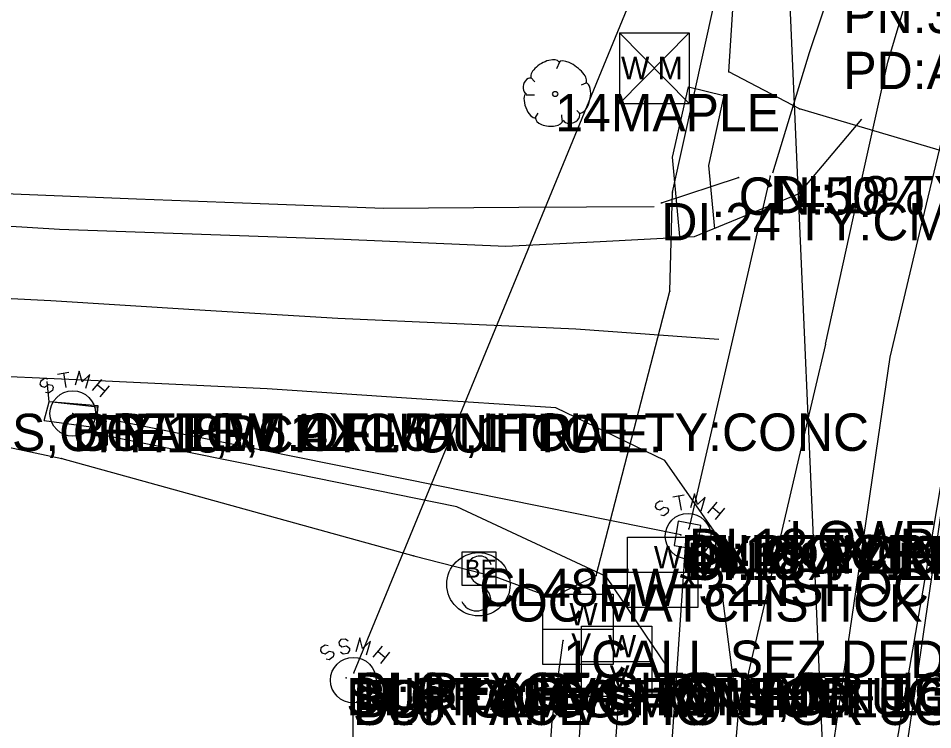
# Model space of a CAD drawing. Extents: x 997398 to 1003416, y 334596 to 337085.
# Drawn here: x 999151.8 to 999274.2, y 335545.4 to 335640.6 of the extents above; entities that cross this region are included whole.
import ezdxf

# ---------------------------------------------------------------- set-up
doc = ezdxf.new("R2010")
doc.units = 0
for name, color, linetype in [('Default', 7, 'Continuous'), ('S_DITCHLINE', 7, 'Continuous'), ('S_DRG_PT_SYM', 7, 'Continuous'), ('S_EDGE_CONCRETE', 7, 'Continuous'), ('S_EDGE_PAVEMENT', 7, 'Continuous'), ('S_ELECTRIC_UTILITIES', 7, 'Continuous'), ('S_ELECTRIC_UTILITIES_ANNOT', 7, 'Continuous'), ('S_FIBER_OPTIC_CABLE', 7, 'Continuous'), ('S_GAS_UTILITIES', 7, 'Continuous'), ('S_GAS_UTILITIES_ANNOT', 7, 'Continuous'), ('S_GRD_PT_SYM', 7, 'Continuous'), ('S_MANHOLE_ANNOT', 7, 'Continuous'), ('S_MISC_TOPO_POINT', 7, 'Continuous'), ('S_PAVEMENT_CROWN', 7, 'Continuous'), ('S_PRIMARY_CTL_ANNOT', 7, 'Continuous'), ('S_SANITARY_SEWER', 7, 'Continuous'), ('S_SANITARY_SEWER_ANNOT', 7, 'Continuous'), ('S_SHOULDER', 7, 'Continuous'), ('S_SIDE_DRAIN', 7, 'Continuous'), ('S_SIDE_DRAIN_ANNOT', 7, 'Continuous'), ('S_SIDEWALK', 7, 'Continuous'), ('S_SIGN', 7, 'Continuous'), ('S_SIGN_ANNOT', 7, 'Continuous'), ('S_STORM_SEWER', 7, 'Continuous'), ('S_STORM_SEWER_ANNOT', 7, 'Continuous'), ('S_TREE', 7, 'Continuous'), ('S_TREE_ANNOT', 7, 'Continuous'), ('S_UTILITY_POLE_ANNOT', 7, 'Continuous'), ('S_UTL_PT_SYM', 7, 'Continuous'), ('S_WATER_UTILITIES', 7, 'Continuous')]:
    doc.layers.add(name, color=color, linetype=linetype)

msp = doc.modelspace()

# ---------------------------------------------------------------- linework, layer by layer
at = {"layer": 'Default'}
msp.add_line((999272.07, 335256.17), (999254.77, 335651.12), dxfattribs=at)
at = {"layer": 'S_DITCHLINE'}
for points in [[(999287.81, 335737.53), (999281.43, 335714.1), (999277.48, 335699.31), (999273.53, 335684.53), (999269.56, 335672.01), (999265.58, 335659.49), (999257.69, 335636), (999252.77, 335619.88)], [(999236.93, 335615.36), (999218.82, 335615.26), (999200.71, 335615.16), (999184.18, 335615.77), (999167.64, 335616.38), (999153.3, 335616.96), (999138.96, 335617.54), (999118.05, 335618.98), (999097.13, 335620.43)]]:
    msp.add_lwpolyline(points, dxfattribs=at)
at = {"layer": 'S_DRG_PT_SYM'}
for points in [[(999248.25, 335619.3), (999248.25, 335619.35), (999248.25, 335619.3), (999248.2, 335619.3), (999248.25, 335619.3), (999248.25, 335619.25), (999248.25, 335619.3), (999248.3, 335619.3)], [(999252.48, 335619.48), (999252.48, 335619.53), (999252.48, 335619.48), (999252.43, 335619.48), (999252.48, 335619.48), (999252.48, 335619.43), (999252.48, 335619.48), (999252.53, 335619.48)], [(999237.91, 335615.88), (999237.91, 335615.93), (999237.91, 335615.88), (999237.86, 335615.88), (999237.91, 335615.88), (999237.91, 335615.83), (999237.91, 335615.88), (999237.96, 335615.88)], [(999241.18, 335570.41), (999241.18, 335570.46), (999241.18, 335570.41), (999241.13, 335570.41), (999241.18, 335570.41), (999241.18, 335570.36), (999241.18, 335570.41), (999241.23, 335570.41)]]:
    msp.add_lwpolyline(points, dxfattribs=at)
at = {"layer": 'S_EDGE_CONCRETE'}
for points in [[(999155.26, 335586.75), (999155.93, 335589.24)], [(999155.26, 335586.75), (999162.22, 335585.84), (999162.48, 335588.73)], [(999162.48, 335588.73), (999155.93, 335589.24)], [(999240.17, 335573.28), (999239.64, 335570.01), (999242.69, 335569.51), (999243.18, 335572.72)], [(999243.18, 335572.72), (999240.17, 335573.28)]]:
    msp.add_lwpolyline(points, dxfattribs=at)
at = {"layer": 'S_EDGE_PAVEMENT'}
for points in [[(999259.87, 335596.96), (999264.04, 335615.85), (999268.21, 335634.73), (999272.57, 335649.27), (999276.93, 335663.8), (999281.3, 335678.34), (999285.66, 335692.87), (999290.47, 335705.41), (999295.28, 335717.95), (999300.08, 335730.5), (999304.89, 335743.04), (999311.07, 335757.48), (999317.24, 335771.92), (999323.96, 335787.59), (999330.67, 335803.27), (999334.33, 335812.1)], [(999077.15, 335619.41), (999094.78, 335617.29), (999112.4, 335615.17), (999134.86, 335613.78), (999157.33, 335612.39), (999176.33, 335611.71), (999195.33, 335611.02), (999217.09, 335610.08), (999229.71, 335610.74), (999242.32, 335611.39), (999256.34, 335617.13), (999264.73, 335627.09)], [(999242.46, 335474.78), (999243.48, 335492.06), (999244.65, 335505.83), (999245.83, 335519.59), (999247.01, 335533.36), (999248.18, 335547.12), (999246.58, 335559.54), (999244.98, 335571.95), (999238.35, 335581.43), (999223.76, 335588.45), (999204.45, 335589.72), (999185.14, 335591), (999163.46, 335592.01), (999141.78, 335593.03), (999120.82, 335594.21), (999099.85, 335595.38), (999086.61, 335596.71), (999073.36, 335598.03)], [(999259.87, 335596.96), (999256.94, 335584.5), (999254.02, 335572.04), (999251.1, 335559.58), (999248.18, 335547.12)], [(999250.53, 335290.61), (999251.9, 335310.31), (999253.28, 335330), (999254.66, 335349.69), (999256.03, 335369.39), (999256.96, 335383.69), (999257.89, 335397.99), (999259.31, 335422.72), (999260.17, 335436.32), (999261.04, 335449.92), (999261.9, 335463.52), (999262.77, 335477.12), (999265.06, 335501.55), (999266.67, 335519.12), (999268.27, 335536.68), (999270.61, 335550.38), (999272.95, 335564.07), (999275.29, 335577.76), (999277.63, 335591.45)], [(999268.87, 335320.6), (999263.53, 335329.26), (999260.4, 335340), (999260.03, 335350.15), (999261.25, 335369.32), (999262.19, 335383.58), (999263.12, 335397.84), (999266.91, 335402.13), (999261.38, 335422.51), (999262.14, 335435.92), (999262.89, 335449.33), (999263.64, 335462.75), (999264.4, 335476.16), (999272.66, 335481.44), (999281.46, 335481.65), (999283.33, 335495.44), (999285.2, 335509.23), (999269.56, 335528.03), (999269.81, 335536.47), (999271.83, 335550.21), (999273.84, 335563.95), (999275.86, 335577.69), (999277.88, 335591.43)]]:
    msp.add_lwpolyline(points, dxfattribs=at)
at = {"layer": 'S_ELECTRIC_UTILITIES'}
msp.add_lwpolyline([(999211.25, 335564.67), (999211.25, 335569.17), (999215.75, 335569.17), (999215.75, 335564.67)], close=True, dxfattribs=at)
at = {"layer": 'S_FIBER_OPTIC_CABLE'}
for p, q in [((999239.4, 335617.34), (999245.02, 335642.72)), ((999246.94, 335633.43), (999247.58, 335643.26)), ((999256.41, 335628.49), (999246.94, 335633.43)), ((999286.13, 335619.67), (999256.41, 335628.49)), ((999239.02, 335604.06), (999239.4, 335617.34)), ((999229.16, 335566.02), (999239.02, 335604.06)), ((999113.2, 335591.12), (999157.62, 335581.67)), ((999157.62, 335581.67), (999204.77, 335568.66)), ((999204.77, 335568.66), (999215.76, 335565.85)), ((999215.76, 335565.85), (999223.21, 335563.09)), ((999223.21, 335563.09), (999229.16, 335566.02))]:
    msp.add_line(p, q, dxfattribs=at)
at = {"layer": 'S_GAS_UTILITIES'}
for p, q in [((999223.28, 335546.56), (999224.76, 335557.3)), ((999220.7, 335507.17), (999223.28, 335546.56))]:
    msp.add_line(p, q, dxfattribs=at)
at = {"layer": 'S_GRD_PT_SYM'}
for points in [[(999161.18, 335587.48), (999161.18, 335587.53), (999161.18, 335587.48), (999161.13, 335587.48), (999161.18, 335587.48), (999161.18, 335587.43), (999161.18, 335587.48), (999161.23, 335587.48)], [(999255.04, 335573.32), (999255.04, 335573.37), (999255.04, 335573.32), (999254.99, 335573.32), (999255.04, 335573.32), (999255.04, 335573.27), (999255.04, 335573.32), (999255.09, 335573.32)], [(999240.51, 335571.44), (999240.51, 335571.49), (999240.51, 335571.44), (999240.46, 335571.44), (999240.51, 335571.44), (999240.51, 335571.39), (999240.51, 335571.44), (999240.56, 335571.44)], [(999241.58, 335572.28), (999241.58, 335572.33), (999241.58, 335572.28), (999241.53, 335572.28), (999241.58, 335572.28), (999241.58, 335572.23), (999241.58, 335572.28), (999241.63, 335572.28)], [(999241.29, 335570.42), (999241.29, 335570.47), (999241.29, 335570.42), (999241.24, 335570.42), (999241.29, 335570.42), (999241.29, 335570.37), (999241.29, 335570.42), (999241.34, 335570.42)], [(999196.73, 335553), (999196.73, 335553.05), (999196.73, 335553), (999196.68, 335553), (999196.73, 335553), (999196.73, 335552.95), (999196.73, 335553), (999196.78, 335553)], [(999195.72, 335552.31), (999195.72, 335552.36), (999195.72, 335552.31), (999195.67, 335552.31), (999195.72, 335552.31), (999195.72, 335552.26), (999195.72, 335552.31), (999195.77, 335552.31)], [(999196.62, 335551), (999196.62, 335551.05), (999196.62, 335551), (999196.57, 335551), (999196.62, 335551), (999196.62, 335550.95), (999196.62, 335551), (999196.67, 335551)]]:
    msp.add_lwpolyline(points, dxfattribs=at)
at = {"layer": 'S_PAVEMENT_CROWN'}
for points in [[(999240.93, 335269.15), (999242.42, 335292.45), (999243.36, 335312.31), (999244.3, 335332.17), (999245.73, 335356.52), (999247.17, 335380.88), (999248.33, 335401.35), (999249.49, 335421.83), (999250.52, 335439.55), (999251.54, 335457.27), (999252.57, 335474.99), (999253.6, 335492.71), (999255.46, 335505.53), (999257.33, 335518.35), (999259.19, 335531.16), (999261.06, 335543.98), (999262.92, 335556.8), (999264.79, 335569.61), (999266.65, 335582.43), (999268.52, 335595.25), (999272.87, 335613.5), (999277.22, 335631.74), (999281.77, 335646.2)], [(999074.89, 335609.01), (999093.33, 335607.02), (999111.77, 335605.03), (999133.96, 335603.93), (999156.15, 335602.83), (999175.37, 335601.64), (999194.6, 335600.46), (999210.53, 335599.74), (999226.46, 335599.02), (999245.58, 335597.67)]]:
    msp.add_lwpolyline(points, dxfattribs=at)
at = {"layer": 'S_SANITARY_SEWER'}
for p, q in [((999196.73, 335553), (999235.68, 335647.6)), ((999192.88, 335556.7), (999192.33, 335556.31)), ((999193.3, 335556.62), (999192.88, 335556.7)), ((999192.33, 335556.31), (999192.26, 335555.92)), ((999192.26, 335555.92), (999192.45, 335555.65)), ((999192.45, 335555.65), (999192.88, 335555.53)), ((999192.88, 335555.53), (999193.42, 335555.88)), ((999193.42, 335555.88), (999193.88, 335555.8)), ((999193.88, 335555.8), (999194.04, 335555.53)), ((999194.04, 335555.53), (999193.96, 335555.11)), ((999199.31, 335555.07), (999200.55, 335556.54)), ((999199.97, 335555.84), (999200.94, 335555.03)), ((999201.52, 335555.73), (999200.28, 335554.25)), ((999193.42, 335554.72), (999193.03, 335554.8)), ((999193.96, 335555.11), (999193.42, 335554.72)), ((999197.31, 335352.9), (999196.62, 335551))]:
    msp.add_line(p, q, dxfattribs=at)
for points in [[(999195.98, 335557.24), (999195.63, 335557.51), (999194.97, 335557.43), (999194.74, 335557.08), (999194.77, 335556.77), (999195.12, 335556.46), (999195.74, 335556.58), (999196.13, 335556.27), (999196.17, 335555.96), (999195.9, 335555.57), (999195.28, 335555.49), (999194.93, 335555.77)], [(999198.42, 335555.38), (999198.96, 335557.24), (999197.91, 335556.23), (999197.53, 335557.66), (999196.98, 335555.8)]]:
    msp.add_lwpolyline(points, dxfattribs=at)
msp.add_circle((999196.66, 335552), 3.05, dxfattribs=at)
at = {"layer": 'S_SHOULDER'}
msp.add_lwpolyline([(999238.81, 335553.62), (999230.53, 335565.88), (999210.52, 335575.21), (999186.37, 335580.1), (999162.21, 335584.98), (999162.42, 335588.53), (999155.93, 335589.24), (999155.69, 335591.99)], dxfattribs=at)
at = {"layer": 'S_SIDE_DRAIN'}
for p, q in [((999237.91, 335615.88), (999248.25, 335619.3)), ((999252.48, 335619.48), (999241.58, 335572.28)), ((999233.26, 335456.06), (999241.18, 335570.41))]:
    msp.add_line(p, q, dxfattribs=at)
at = {"layer": 'S_SIDEWALK'}
for points in [[(999240.36, 335611.38), (999239.4, 335622.03), (999241.55, 335631.45), (999246.25, 335630.25), (999244.2, 335620.92), (999245.02, 335612.43)], [(999214.01, 335280.58), (999214.8, 335292.62), (999216.16, 335313.46), (999217.52, 335334.3), (999218.07, 335347.06), (999218.63, 335359.82), (999222.21, 335371.88), (999225.78, 335383.94), (999224.2, 335403.9), (999222.62, 335423.86), (999222.83, 335441.35), (999223.04, 335458.84), (999223.26, 335476.33), (999223.47, 335493.82), (999224.42, 335507.61), (999225.37, 335521.4), (999226.32, 335535.18), (999227.27, 335548.97)], [(999225.73, 335271.38), (999218.89, 335281.67), (999219.66, 335292.48), (999220.98, 335313.22), (999222.31, 335333.97), (999223.3, 335346.79), (999224.29, 335359.6), (999230.64, 335383.76), (999229.05, 335404.13), (999227.47, 335424.5), (999227.67, 335441.74), (999227.86, 335458.99), (999228.06, 335476.23), (999228.26, 335493.48), (999229.22, 335507.16), (999230.18, 335520.85), (999231.14, 335534.54), (999232.1, 335548.22)]]:
    msp.add_lwpolyline(points, dxfattribs=at)
at = {"layer": 'S_SIGN'}
msp.add_circle((999213.42, 335564.84), 4.24, dxfattribs=at)
for centre, radius, start, end in [((999213.55, 335567), 1.62, 16.5258, 156.8957), ((999214.58, 335567.1), 2.55, 167.1196, 241.9813), ((999212.72, 335562.56), 2.38, 358.6529, 73.7063), ((999213.16, 335563.44), 2.17, 204.641, 335.359)]:
    msp.add_arc(centre, radius, start, end, dxfattribs=at)
at = {"layer": 'S_STORM_SEWER'}
for p, q in [((999155.32, 335592.39), (999154.78, 335592)), ((999155.74, 335592.31), (999155.32, 335592.39)), ((999157.06, 335592.97), (999158.57, 335593.24)), ((999157.84, 335593.13), (999158.19, 335591.19)), ((999161.75, 335590.76), (999162.99, 335592.24)), ((999154.78, 335592), (999154.7, 335591.62)), ((999154.7, 335591.62), (999154.89, 335591.35)), ((999154.89, 335591.35), (999155.32, 335591.23)), ((999155.32, 335591.23), (999155.86, 335591.58)), ((999155.86, 335591.58), (999156.33, 335591.5)), ((999156.33, 335591.5), (999156.48, 335591.23)), ((999156.48, 335591.23), (999156.4, 335590.8)), ((999162.41, 335591.54), (999163.38, 335590.73)), ((999163.96, 335591.42), (999162.72, 335589.95)), ((999155.86, 335590.42), (999155.47, 335590.49)), ((999156.4, 335590.8), (999155.86, 335590.42)), ((999240.51, 335571.44), (999161.18, 335587.48)), ((999239.44, 335576.56), (999240.95, 335576.83)), ((999240.21, 335576.71), (999240.56, 335574.77)), ((999237.15, 335575.59), (999237.07, 335575.2)), ((999237.07, 335575.2), (999237.27, 335574.93)), ((999237.69, 335575.97), (999237.15, 335575.59)), ((999238.12, 335575.9), (999237.69, 335575.97)), ((999237.69, 335574.81), (999238.24, 335575.16)), ((999238.24, 335575.16), (999238.7, 335575.08)), ((999238.7, 335575.08), (999238.86, 335574.81)), ((999244.13, 335574.35), (999245.37, 335575.82)), ((999244.79, 335575.12), (999245.75, 335574.31)), ((999237.27, 335574.93), (999237.69, 335574.81)), ((999238.24, 335574), (999237.85, 335574.08)), ((999238.78, 335574.39), (999238.24, 335574)), ((999238.86, 335574.81), (999238.78, 335574.39)), ((999246.34, 335575.01), (999245.1, 335573.53))]:
    msp.add_line(p, q, dxfattribs=at)
for points in [[(999160.86, 335591.07), (999161.4, 335592.93), (999160.36, 335591.93), (999159.97, 335593.36), (999159.43, 335591.5)], [(999243.24, 335574.66), (999243.78, 335576.52), (999242.73, 335575.51), (999242.34, 335576.94), (999241.8, 335575.08)]]:
    msp.add_lwpolyline(points, dxfattribs=at)
for centre in [(999159.1, 335587.7), (999241.48, 335571.28)]:
    msp.add_circle(centre, 3.05, dxfattribs=at)
at = {"layer": 'S_TREE'}
for p, q in [((999224.25, 335634.72), (999223.86, 335633.86)), ((999220.45, 335632.7), (999220.95, 335632.12)), ((999227.81, 335631.93), (999227.15, 335631.66)), ((999219.79, 335630.38), (999220.91, 335630.38)), ((999220.95, 335627.2), (999221.42, 335627.9)), ((999224.63, 335626.93), (999224.56, 335627.7)), ((999227.04, 335627.82), (999226.57, 335628.25))]:
    msp.add_line(p, q, dxfattribs=at)
msp.add_circle((999223.69, 335630.47), 0.341, dxfattribs=at)
for centre, major_axis, ratio, start_param, end_param in [((999222.35, 335633.67), (1.86, 1.08), 0.471018, 0, 3.141593), ((999226.01, 335633.35), (-1.81, 1.36), 0.405113, 3.141593, 6.283186), ((999220.12, 335631.56), (0.31, 1.03), 0.646762, 0, 3.141593), ((999227.36, 335629.94), (0.46, 2.04), 0.482994, 3.141593, 6.283185), ((999220.42, 335628.91), (-0.61, 1.6), 0.420543, 6.283185, 9.424777), ((999225.84, 335627.42), (1.09, 0.46), 0.711534, 3.141592, 6.283185), ((999222.88, 335627.13), (-1.83, 0.19), 0.529943, 0, 3.141593)]:
    msp.add_ellipse(centre, major_axis=major_axis, ratio=ratio, start_param=start_param, end_param=end_param, dxfattribs=at)
at = {"layer": 'S_UTL_PT_SYM'}
for points in [[(999246.94, 335633.43), (999246.94, 335633.48), (999246.94, 335633.43), (999246.89, 335633.43), (999246.94, 335633.43), (999246.94, 335633.38), (999246.94, 335633.43), (999246.99, 335633.43)], [(999256.41, 335628.49), (999256.41, 335628.54), (999256.41, 335628.49), (999256.36, 335628.49), (999256.41, 335628.49), (999256.41, 335628.44), (999256.41, 335628.49), (999256.46, 335628.49)], [(999239.4, 335617.34), (999239.4, 335617.39), (999239.4, 335617.34), (999239.35, 335617.34), (999239.4, 335617.34), (999239.4, 335617.29), (999239.4, 335617.34), (999239.45, 335617.34)], [(999239.02, 335604.06), (999239.02, 335604.11), (999239.02, 335604.06), (999238.97, 335604.06), (999239.02, 335604.06), (999239.02, 335604.01), (999239.02, 335604.06), (999239.07, 335604.06)], [(999159.1, 335587.7), (999159.1, 335587.75), (999159.1, 335587.7), (999159.05, 335587.7), (999159.1, 335587.7), (999159.1, 335587.65), (999159.1, 335587.7), (999159.15, 335587.7)], [(999161.18, 335587.48), (999161.18, 335587.53), (999161.18, 335587.48), (999161.13, 335587.48), (999161.18, 335587.48), (999161.18, 335587.43), (999161.18, 335587.48), (999161.23, 335587.48)], [(999157.62, 335581.67), (999157.62, 335581.72), (999157.62, 335581.67), (999157.57, 335581.67), (999157.62, 335581.67), (999157.62, 335581.62), (999157.62, 335581.67), (999157.67, 335581.67)], [(999255.04, 335573.32), (999255.04, 335573.37), (999255.04, 335573.32), (999254.99, 335573.32), (999255.04, 335573.32), (999255.04, 335573.27), (999255.04, 335573.32), (999255.09, 335573.32)], [(999240.51, 335571.44), (999240.51, 335571.49), (999240.51, 335571.44), (999240.46, 335571.44), (999240.51, 335571.44), (999240.51, 335571.39), (999240.51, 335571.44), (999240.56, 335571.44)], [(999241.58, 335572.28), (999241.58, 335572.33), (999241.58, 335572.28), (999241.53, 335572.28), (999241.58, 335572.28), (999241.58, 335572.23), (999241.58, 335572.28), (999241.63, 335572.28)], [(999241.29, 335570.42), (999241.29, 335570.47), (999241.29, 335570.42), (999241.24, 335570.42), (999241.29, 335570.42), (999241.29, 335570.37), (999241.29, 335570.42), (999241.34, 335570.42)], [(999241.48, 335571.28), (999241.48, 335571.33), (999241.48, 335571.28), (999241.43, 335571.28), (999241.48, 335571.28), (999241.48, 335571.23), (999241.48, 335571.28), (999241.53, 335571.28)], [(999204.77, 335568.66), (999204.77, 335568.71), (999204.77, 335568.66), (999204.72, 335568.66), (999204.77, 335568.66), (999204.77, 335568.61), (999204.77, 335568.66), (999204.82, 335568.66)], [(999215.76, 335565.85), (999215.76, 335565.9), (999215.76, 335565.85), (999215.71, 335565.85), (999215.76, 335565.85), (999215.76, 335565.8), (999215.76, 335565.85), (999215.81, 335565.85)], [(999229.16, 335566.02), (999229.16, 335566.07), (999229.16, 335566.02), (999229.11, 335566.02), (999229.16, 335566.02), (999229.16, 335565.97), (999229.16, 335566.02), (999229.21, 335566.02)], [(999223.21, 335563.09), (999223.21, 335563.14), (999223.21, 335563.09), (999223.16, 335563.09), (999223.21, 335563.09), (999223.21, 335563.04), (999223.21, 335563.09), (999223.26, 335563.09)], [(999224.76, 335557.3), (999224.76, 335557.35), (999224.76, 335557.3), (999224.71, 335557.3), (999224.76, 335557.3), (999224.76, 335557.25), (999224.76, 335557.3), (999224.81, 335557.3)], [(999196.73, 335553), (999196.73, 335553.05), (999196.73, 335553), (999196.68, 335553), (999196.73, 335553), (999196.73, 335552.95), (999196.73, 335553), (999196.78, 335553)], [(999195.72, 335552.31), (999195.72, 335552.36), (999195.72, 335552.31), (999195.67, 335552.31), (999195.72, 335552.31), (999195.72, 335552.26), (999195.72, 335552.31), (999195.77, 335552.31)], [(999196.66, 335552), (999196.66, 335552.05), (999196.66, 335552), (999196.61, 335552), (999196.66, 335552), (999196.66, 335551.96), (999196.66, 335552), (999196.71, 335552)], [(999196.62, 335551), (999196.62, 335551.05), (999196.62, 335551), (999196.57, 335551), (999196.62, 335551), (999196.62, 335550.95), (999196.62, 335551), (999196.67, 335551)], [(999223.28, 335546.56), (999223.28, 335546.61), (999223.28, 335546.56), (999223.23, 335546.56), (999223.28, 335546.56), (999223.28, 335546.51), (999223.28, 335546.56), (999223.33, 335546.56)]]:
    msp.add_lwpolyline(points, dxfattribs=at)
at = {"layer": 'S_WATER_UTILITIES'}
for p, q in [((999232.3, 335638.68), (999241.64, 335638.68)), ((999232.3, 335638.68), (999232.3, 335629.19)), ((999232.3, 335638.68), (999241.64, 335629.19)), ((999241.64, 335638.68), (999232.3, 335629.19)), ((999241.64, 335638.68), (999241.64, 335629.19)), ((999232.3, 335629.19), (999241.64, 335629.19)), ((999233.35, 335571.13), (999242.77, 335571.13)), ((999233.35, 335561.71), (999233.35, 335571.13)), ((999242.77, 335571.13), (999242.77, 335561.71)), ((999233.35, 335566.44), (999242.77, 335566.44)), ((999222.05, 335563.5), (999231.46, 335563.5)), ((999222.05, 335554.08), (999222.05, 335563.5)), ((999231.46, 335563.5), (999231.46, 335554.08)), ((999242.77, 335561.71), (999233.35, 335561.71)), ((999227.2, 335559.21), (999236.61, 335559.21)), ((999227.2, 335549.8), (999227.2, 335559.21)), ((999236.61, 335559.21), (999236.61, 335549.8)), ((999222.05, 335558.81), (999231.46, 335558.81)), ((999227.2, 335554.52), (999236.61, 335554.52)), ((999231.46, 335554.08), (999222.05, 335554.08)), ((999236.61, 335549.8), (999227.2, 335549.8))]:
    msp.add_line(p, q, dxfattribs=at)

# ---------------------------------------------------------------- texts
at = {"layer": 'S_ELECTRIC_UTILITIES'}
msp.add_text('BE', height=2.4, rotation=360, dxfattribs=at).set_placement((999211.56, 335565.72))
at = {"layer": 'S_ELECTRIC_UTILITIES_ANNOT'}
for s, p in [('LOWEST WIRE', (999255.04, 335568.32)), ('CL48EW*32NSFOC VAULT', (999213.52, 335561.92))]:
    msp.add_text(s, height=5, dxfattribs=at).set_placement(p)
at = {"layer": 'S_GAS_UTILITIES_ANNOT'}
msp.add_text('1CALL SEZ DED LINE CONT S 1CALL', height=5, dxfattribs=at).set_placement((999224.76, 335552.3))
at = {"layer": 'S_MANHOLE_ANNOT'}
for s, p in [('BOTTOM OF MANHOLE TY:CONC', (999159.1, 335582.7)), ('TY:CONC BOTTOM OF MANHOLE', (999241.48, 335566.28)), ('BOTTOM OF MANHOLE', (999196.66, 335547.01))]:
    msp.add_text(s, height=5, dxfattribs=at).set_placement(p)
at = {"layer": 'S_MISC_TOPO_POINT'}
for p in [(999240.51, 335566.44), (999196.73, 335548), (999195.72, 335547.31), (999196.62, 335546)]:
    msp.add_text('SURFACE SHOT FOR UG PIPE', height=5, dxfattribs=at).set_placement(p)
at = {"layer": 'S_PRIMARY_CTL_ANNOT'}
for s, p in [('PN:3', (999262.27, 335638.62)), ('PD:AHTD STD. MON. STAMPED PN 3', (999262.27, 335631.12))]:
    msp.add_text(s, height=5, dxfattribs=at).set_placement(p)
at = {"layer": 'S_SANITARY_SEWER_ANNOT'}
for s, p in [('DI:6 TY:PVC TO NNE', (999196.73, 335548)), ('DI:6 TY:PVC TO W,C/N LOCATE NEXT', (999195.72, 335547.31)), ('TOP CL OF MANHOLE', (999196.66, 335547.01)), ('DI:6 TY:PVC TO S', (999196.62, 335546))]:
    msp.add_text(s, height=5, dxfattribs=at).set_placement(p)
at = {"layer": 'S_SIDE_DRAIN_ANNOT'}
for s, p in [('CN:50% FILL,CRUSHED', (999248.25, 335614.3)), ('DI:18 TY:RCP CN:50% FILL,CONT.N', (999252.48, 335614.48)), ('DI:24 TY:CMP,CRUSHED CN:50% FIL', (999237.91, 335610.88)), ('CN:0% FILL', (999241.18, 335565.41))]:
    msp.add_text(s, height=5, dxfattribs=at).set_placement(p)
at = {"layer": 'S_SIGN_ANNOT'}
msp.add_text('FOC MATCHSTICK', height=5, dxfattribs=at).set_placement((999213.42, 335559.84))
at = {"layer": 'S_STORM_SEWER_ANNOT'}
for s, p in [('GRATE,5.4X1.5', (999159.1, 335582.7)), ('TY:18RCP FL OUT TO E.', (999161.18, 335582.48)), ('DI:18 TY:RCP TO W.', (999240.51, 335566.44)), ('DI:18 TY:RCP TO N.', (999241.58, 335567.28)), ('CL 2.0X2.0 GR8', (999241.48, 335566.28)), ('DI:18 TY:RCP TO S.', (999241.29, 335565.42))]:
    msp.add_text(s, height=5, dxfattribs=at).set_placement(p)
at = {"layer": 'S_TREE_ANNOT'}
msp.add_text('14MAPLE', height=5, dxfattribs=at).set_placement((999223.69, 335625.47))
at = {"layer": 'S_UTILITY_POLE_ANNOT'}
msp.add_text('1LGT,1TRANS,OHE E,W 1LIGHT,1TRA', height=5, dxfattribs=at).set_placement((999110.47, 335582.67))
at = {"layer": 'S_WATER_UTILITIES'}
for s, p in [('W M', (999232.51, 335632.45)), ('W', (999236.9, 335566.97)), ('V', (999237.14, 335562.91)), ('W', (999225.6, 335559.34)), ('V', (999225.83, 335555.28)), ('W', (999230.75, 335555.05)), ('V', (999230.98, 335550.99))]:
    msp.add_text(s, height=3, rotation=360, dxfattribs=at).set_placement(p)

doc.saveas('drawing.dxf')
